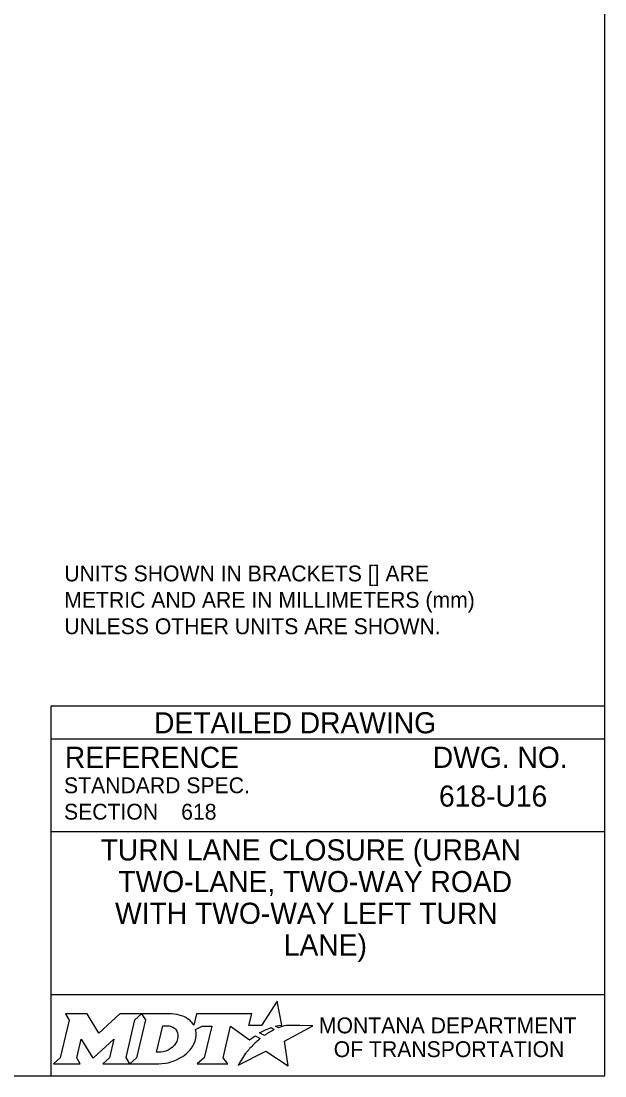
# Model space of a CAD drawing. Extents: x 49991.4 to 50021, y 49987.6 to 50011.4.
# Drawn here: x 50006.402 to 50008.615, y 50000.062 to 50004.057 of the extents above; entities that cross this region are included whole.
import ezdxf

# ---------------------------------------------------------------- set-up
doc = ezdxf.new("R2010")
doc.units = 0
doc.layers.add('Level 1', color=7, linetype='Continuous')
doc.layers.add('Level 2', color=7, linetype='Continuous')

msp = doc.modelspace()

# ---------------------------------------------------------------- linework, layer by layer
at = {"layer": 'Level 1'}
msp.add_lwpolyline([(50008.6146, 50011.2628), (50000.3356, 50011.2628), (50000.3356, 50000.0624), (50008.6146, 50000.0624)], close=True, dxfattribs=at)
at = {"layer": 'Level 2'}
for p, q in [((50008.6146, 50001.4624), (50006.5146, 50001.4624)), ((50006.5146, 50001.4624), (50006.5146, 50000.0624)), ((50008.6146, 50001.3374), (50006.5146, 50001.3374)), ((50008.2507, 50001.1223), (50008.2507, 50001.1223)), ((50007.0089, 50001.0629), (50007.0089, 50001.0629)), ((50008.6146, 50000.9874), (50006.5146, 50000.9874)), ((50007.5646, 50000.7383), (50007.5646, 50000.7383)), ((50008.6146, 50000.3693), (50006.5146, 50000.3693))]:
    msp.add_line(p, q, dxfattribs=at)
for points in [[(50007.3771, 50000.2447), (50007.3668, 50000.2503), (50007.3784, 50000.2531), (50007.39, 50000.2551), (50007.3726, 50000.3452), (50007.3131, 50000.2539), (50007.2658, 50000.2532), (50007.2761, 50000.2973), (50007.0669, 50000.2974), (50007.0568, 50000.2549), (50007.051, 50000.2632)], [(50006.5701, 50000.2974), (50006.5842, 50000.274), (50006.5507, 50000.1307), (50006.525, 50000.1082), (50006.6266, 50000.1082), (50006.6131, 50000.131), (50006.6293, 50000.2011), (50006.673, 50000.1321), (50006.6783, 50000.1321), (50006.7534, 50000.2016), (50006.737, 50000.1305), (50006.7123, 50000.1085), (50006.8139, 50000.1085), (50006.8001, 50000.1318), (50006.8333, 50000.2742)], [(50006.8333, 50000.2742), (50006.8586, 50000.2974), (50006.7762, 50000.2974), (50006.6966, 50000.2244), (50006.6521, 50000.2971), (50006.5701, 50000.2974)], [(50006.9722, 50000.2974), (50006.8586, 50000.2974), (50006.8733, 50000.2745), (50006.8394, 50000.1307), (50006.8139, 50000.1085), (50006.9245, 50000.1085)], [(50006.9962, 50000.2107), (50006.995, 50000.2026), (50006.9918, 50000.1933), (50006.9876, 50000.1851), (50006.982, 50000.1776), (50006.9755, 50000.1707), (50006.9676, 50000.1644), (50006.9593, 50000.1597), (50006.9502, 50000.1558), (50006.9411, 50000.1535), (50006.9319, 50000.1526), (50006.916, 50000.1526), (50006.9396, 50000.2526), (50006.9556, 50000.2526), (50006.9632, 50000.252), (50006.9708, 50000.2501), (50006.9774, 50000.2471), (50006.9835, 50000.2429), (50006.9883, 50000.2379), (50006.992, 50000.2319), (50006.9947, 50000.2257), (50006.9963, 50000.2183), (50006.9963, 50000.2153), (50006.9962, 50000.2107)], [(50007.0636, 50000.2383), (50007.0882, 50000.2514), (50007.1251, 50000.2514), (50007.0965, 50000.1309), (50007.069, 50000.1082), (50007.1852, 50000.1082), (50007.1682, 50000.1311), (50007.1964, 50000.2513), (50007.2677, 50000.1996), (50007.2888, 50000.2147), (50007.3085, 50000.2038)], [(50007.2527, 50000.1479), (50007.2374, 50000.1235), (50007.2327, 50000.116), (50007.2269, 50000.1074), (50007.2246, 50000.1031), (50007.3299, 50000.1562), (50007.4138, 50000.1011), (50007.4007, 50000.1938), (50007.5076, 50000.2522), (50007.4583, 50000.253), (50007.4282, 50000.2534), (50007.4074, 50000.2537), (50007.4006, 50000.2522), (50007.3957, 50000.251), (50007.3873, 50000.2487), (50007.3771, 50000.2447)], [(50007.3267, 50000.2171), (50007.3243, 50000.2154), (50007.306, 50000.225), (50007.3163, 50000.2307), (50007.3204, 50000.2329), (50007.329, 50000.2369), (50007.3347, 50000.2395), (50007.3426, 50000.2425), (50007.3499, 50000.2452), (50007.3617, 50000.2378), (50007.3577, 50000.2357), (50007.3531, 50000.2332), (50007.3489, 50000.231), (50007.3439, 50000.2281), (50007.342, 50000.227), (50007.3393, 50000.2254), (50007.3368, 50000.224), (50007.3345, 50000.2224), (50007.3319, 50000.2206), (50007.3292, 50000.2188), (50007.3267, 50000.2171)], [(50007.2666, 50000.164), (50007.2666, 50000.164)], [(50006.9702, 50000.1158), (50006.9786, 50000.1184), (50006.9916, 50000.1238), (50007.012, 50000.1348)]]:
    msp.add_lwpolyline(points, dxfattribs=at)
for centre, radius, start, end in [((50006.9953, 50000.219), 0.0709, 339.5329, 15.8582), ((50006.9513, 50000.2363), 0.1183, 300.9103, 339.1383)]:
    msp.add_arc(centre, radius, start, end, dxfattribs=at)
for centre, major_axis, ratio, start_param, end_param in [((50006.9701, 50000.25), (0.0834, -0.0037), 0.568097, 0.61298, 1.570796), ((50007.0257, 50000.2573), (0.0361, -0.0295), 0.469099, 1.225588, 1.570796), ((50007.2974, 50000.1941), (-0.0112, -0.0097), 0.021651, 3.157348, 6.283185), ((50007.2597, 50000.1559), (-0.00694, -0.00806), 0.008222, 0, 3.137361), ((50007.2764, 50000.1742), (-0.0098, -0.0102), 0.016458, 3.141593, 6.279097), ((50006.9248, 50000.2568), (0, 0.1484), 0.987302, 3.139398, 3.456847)]:
    msp.add_ellipse(centre, major_axis=major_axis, ratio=ratio, start_param=start_param, end_param=end_param, dxfattribs=at)

# ---------------------------------------------------------------- texts
for s, height, p in [('UNITS SHOWN IN BRACKETS [] ARE ', 0.06, (50006.5658, 50001.9354)), ('METRIC AND ARE IN MILLIMETERS (mm) ', 0.06, (50006.5658, 50001.8354)), ('UNLESS OTHER UNITS ARE SHOWN.', 0.06, (50006.5658, 50001.7354)), ('DETAILED DRAWING', 0.0799, (50006.9063, 50001.3599)), ('REFERENCE', 0.08, (50006.5682, 50001.229)), ('DWG. NO.', 0.08, (50007.9624, 50001.229)), ('STANDARD SPEC.', 0.06, (50006.5649, 50001.133)), ('618-U16', 0.08, (50007.9858, 50001.0823)), ('SECTION', 0.06, (50006.5649, 50001.033)), ('618', 0.06, (50007.0089, 50001.0329)), ('TURN LANE CLOSURE (URBAN', 0.08, (50006.7035, 50000.8783)), ('TWO-LANE, TWO-WAY ROAD ', 0.08, (50006.7709, 50000.7583)), ('WITH TWO-WAY LEFT TURN ', 0.08, (50006.7584, 50000.6383)), ('LANE)', 0.08, (50007.3978, 50000.5183)), ('MONTANA DEPARTMENT', 0.06, (50007.5308, 50000.2236)), ('OF TRANSPORTATION', 0.06, (50007.587, 50000.1336))]:
    msp.add_text(s, height=height, dxfattribs=at).set_placement(p)

doc.saveas('drawing.dxf')
